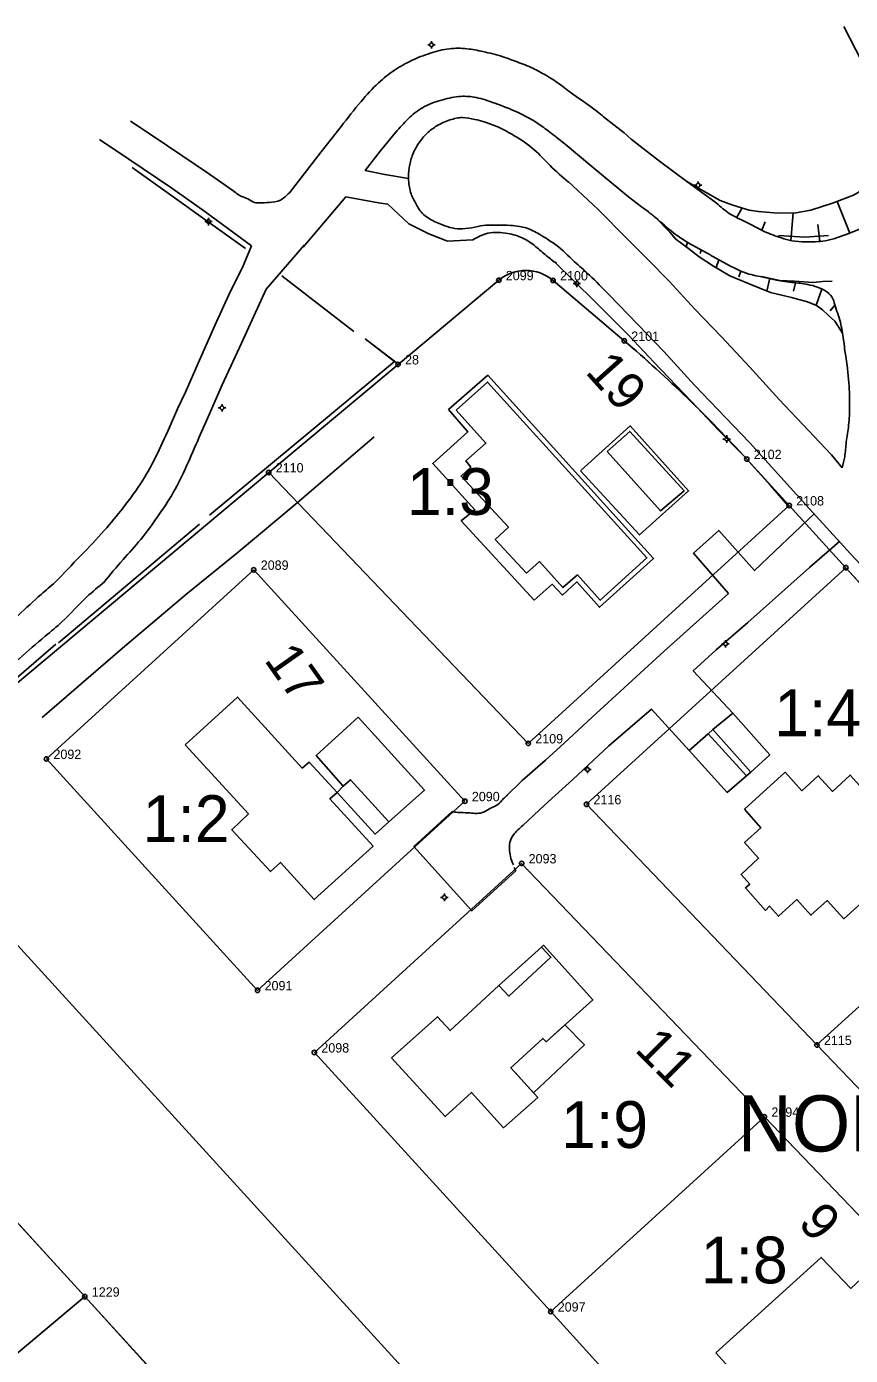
# Model space of a CAD drawing. Extents: x 1517693 to 1518189, y 6494860 to 6495280.
# Drawn here: x 1517936.6 to 1518024.6, y 6495135.7 to 6495277.8 of the extents above; entities that cross this region are included whole.
import ezdxf

# ---------------------------------------------------------------- set-up
doc = ezdxf.new("R2010")
doc.units = 0
for name, color, linetype in [('adress', 7, 'Continuous'), ('bostadshus', 7, 'Continuous'), ('fastighetsbeteckning', 7, 'Continuous'), ('gc_vag', 7, 'Continuous'), ('grans', 7, 'Continuous'), ('granspunkt', 7, 'Continuous'), ('granspunkt_text', 7, 'Continuous'), ('hack', 7, 'Continuous'), ('kvartersgrans', 7, 'Continuous'), ('kvartersgrans_utan_fastgr', 7, 'Continuous'), ('kvartersnamn', 7, 'Continuous'), ('skarmtak', 7, 'Continuous'), ('slant_skraffering', 7, 'Continuous'), ('slantfot', 7, 'Continuous'), ('slantkron', 7, 'Continuous'), ('staket', 7, 'Continuous'), ('stenmur', 7, 'Continuous'), ('stolpe_belysning', 7, 'Continuous'), ('uthus', 7, 'Continuous'), ('vagkant', 7, 'Continuous')]:
    doc.layers.add(name, color=color, linetype=linetype)

msp = doc.modelspace()

# ---------------------------------------------------------------- linework, layer by layer
at = {"layer": 'bostadshus'}
for points in [[(1517982.48, 6495236.79), (1517985.82, 6495239.79), (1518002.87, 6495221.01), (1517997.88, 6495216.47), (1517995.44, 6495219.18), (1517993.9, 6495217.82), (1517991.38, 6495220.6), (1517989.99, 6495219.38), (1517986.66, 6495222.97), (1517988.07, 6495224.27), (1517983.01, 6495229.73), (1517984.06, 6495230.71), (1517983.52, 6495231.36), (1517985.66, 6495233.27), (1517982.48, 6495236.79)], [(1517953.5, 6495201.02), (1517959.1, 6495206.11), (1517966.02, 6495198.53), (1517966.76, 6495199.15), (1517969.76, 6495195.93), (1517968.99, 6495195.25), (1517973.6, 6495190.18), (1517967.31, 6495184.46), (1517963.71, 6495188.43), (1517962.62, 6495187.46), (1517958.49, 6495191.93), (1517960.28, 6495193.62), (1517953.5, 6495201.02)], [(1518013.29, 6495194.12), (1518017.64, 6495198.07), (1518019.42, 6495196.1), (1518021.19, 6495197.7), (1518022.7, 6495196.02), (1518024.6, 6495197.78), (1518028.63, 6495193.3)], [(1518028.31, 6495186.35), (1518023.92, 6495182.41), (1518022.16, 6495184.36), (1518020.4, 6495182.79), (1518018.9, 6495184.47), (1518016.93, 6495182.68), (1518015.98, 6495183.76), (1518015.54, 6495183.31), (1518013.4, 6495185.71), (1518013.86, 6495186.11), (1518012.94, 6495187.14), (1518014.82, 6495188.89), (1518013.31, 6495190.58), (1518015.04, 6495192.12), (1518013.29, 6495194.12)], [(1517975.57, 6495167.55), (1517980.48, 6495171.93), (1517981.83, 6495170.45), (1517987.06, 6495175.28), (1517988.1, 6495174.14), (1517992.61, 6495178.29), (1517991.59, 6495179.38), (1517991.82, 6495179.58), (1517997.11, 6495173.74), (1517992.09, 6495169.26), (1517991.75, 6495169.62), (1517988.32, 6495166.48), (1517991.2, 6495163.3), (1517987.55, 6495160.07), (1517984.13, 6495163.84), (1517981.3, 6495161.27), (1517975.57, 6495167.55)], [(1518010.24, 6495136.01), (1518021.49, 6495146.21), (1518024.66, 6495142.89), (1518028.99, 6495146.91), (1518039.53, 6495135.57), (1518028.29, 6495125.18), (1518029.76, 6495123.58), (1518022.02, 6495116.58), (1518022.18, 6495116.39), (1518018.47, 6495113.08), (1518013.52, 6495118.58), (1518022.53, 6495126.88), (1518015.48, 6495134.51), (1518013.35, 6495132.59), (1518010.23, 6495136.01)]]:
    msp.add_lwpolyline(points, dxfattribs=at)
at = {"layer": 'gc_vag'}
for p, q in [((1517965.26, 6495260.82), (1517964.65, 6495260.03)), ((1517970.67, 6495259.61), (1517966.11, 6495254.21))]:
    msp.add_line(p, q, dxfattribs=at)
for points in [[(1517998.25, 6495268.16), (1518000.45, 6495266.43), (1518001.2, 6495265.76)], [(1517958.87, 6495260.1), (1517955.99, 6495262.08), (1517950.2, 6495266.03), (1517947.68, 6495267.69)], [(1517970.19, 6495267.12), (1517968.06, 6495264.42), (1517965.26, 6495260.82)], [(1517976.19, 6495266.7), (1517974.34, 6495264.49), (1517972.76, 6495262.43), (1517974.85, 6495261.97), (1517977.4, 6495261.55)], [(1517947.49, 6495263.61), (1517944.35, 6495265.74)], [(1517993.91, 6495265.4), (1517997.19, 6495262.67), (1517999.04, 6495261.12), (1518000.89, 6495259.61), (1518002.28, 6495258.52), (1518002.99, 6495258.03)], [(1518010.15, 6495259.08), (1518007.15, 6495261.25), (1518004.22, 6495263.42), (1518001.2, 6495265.76)], [(1517960.6, 6495254.37), (1517955.6, 6495258.02), (1517952.07, 6495260.53), (1517947.49, 6495263.61)], [(1517975.17, 6495258.82), (1517974.19, 6495258.97), (1517970.67, 6495259.61)], [(1517975.17, 6495258.82), (1517977.41, 6495256.72), (1517979.57, 6495255.64), (1517981.57, 6495254.87), (1517984.25, 6495255)], [(1517960.6, 6495254.37), (1517959.63, 6495252.05), (1517958.37, 6495249.52), (1517956.69, 6495245.83), (1517954.9, 6495241.83), (1517953.53, 6495238.72), (1517952.69, 6495236.93), (1517951.8, 6495234.88)], [(1517966.27, 6495254.47), (1517962.16, 6495249.73), (1517959.53, 6495243.94), (1517957.48, 6495239.51), (1517955.85, 6495235.83), (1517954.98, 6495233.83)], [(1517993.02, 6495252.63), (1517997.24, 6495248.49), (1518000.94, 6495244.79), (1518003.63, 6495241.91)], [(1518003.63, 6495241.88), (1518003.63, 6495241.91), (1518007.63, 6495237.7), (1518010.48, 6495234.7), (1518013.14, 6495232.03), (1518016.08, 6495228.73), (1518017.93, 6495226.61)], [(1518020.74, 6495225.7), (1518014.37, 6495219.64), (1518010.55, 6495223.93), (1518007.87, 6495221.49), (1518011.61, 6495217.19)], [(1518023.5, 6495222.78), (1518020.24, 6495219.96), (1518013.66, 6495214.09)], [(1518011.61, 6495217.19), (1518004.71, 6495211.01), (1517997.03, 6495203.95)], [(1518013.66, 6495214.09), (1518010.26, 6495211.17), (1518007.82, 6495208.93), (1518012.07, 6495204.4)], [(1518007.39, 6495200.41), (1518003.36, 6495204.82), (1517998.81, 6495200.9), (1517994.94, 6495197.32)], [(1517987.77, 6495195.46), (1517989.52, 6495197.19), (1517992.05, 6495199.37), (1517994.02, 6495201.19), (1517997.03, 6495203.95)], [(1517994.94, 6495197.32), (1517991.91, 6495194.55), (1517989.62, 6495192.39)], [(1517988.68, 6495187.89), (1517988.86, 6495187.55), (1517984.15, 6495183.26), (1517977.97, 6495190.13), (1517982.05, 6495193.87)]]:
    msp.add_lwpolyline(points, dxfattribs=at)
for points in [[(1517970.19, 6495267.12), (1517972.31, 6495269.79), (1517974.19, 6495271.79), (1517975.88, 6495273.13), (1517977.7, 6495274.16), (1517979.7, 6495274.95), (1517981.76, 6495275.43), (1517983.64, 6495275.43), (1517985.34, 6495275.13), (1517987.46, 6495274.58), (1517988.79, 6495274.1), (1517990.49, 6495273.43), (1517991.89, 6495272.7), (1517993.34, 6495271.79), (1517994.8, 6495270.7), (1517996.86, 6495269.25), (1517998.25, 6495268.16)], [(1517976.19, 6495266.7), (1517977.52, 6495268.1), (1517979.1, 6495269.25), (1517981.04, 6495269.98), (1517982.98, 6495270.34), (1517984.61, 6495270.22), (1517986.61, 6495269.61), (1517989.04, 6495268.64), (1517990.67, 6495267.79), (1517992.01, 6495266.88), (1517994.1, 6495265.25)], [(1517964.65, 6495260.03), (1517963.69, 6495259.26), (1517962.48, 6495259), (1517961.53, 6495258.95), (1517960.91, 6495259), (1517960.22, 6495259.37), (1517959.48, 6495259.68), (1517958.48, 6495260.37)], [(1518002.9, 6495258.1), (1518003.79, 6495257.38), (1518005.71, 6495255.76), (1518007.62, 6495254.49), (1518009.19, 6495253.64), (1518010.77, 6495252.74), (1518012.34, 6495251.93), (1518013.53, 6495251.42), (1518014.51, 6495251.17), (1518018.34, 6495250.45), (1518020.08, 6495250.23), (1518021.1, 6495249.94), (1518022.12, 6495249.43), (1518022.76, 6495248.7), (1518023.02, 6495247.85), (1518023.36, 6495246.87), (1518023.78, 6495245.04), (1518024.04, 6495243.13)], [(1518029.88, 6495259.08), (1518028.1, 6495257.68), (1518026.44, 6495256.57), (1518024.36, 6495255.64), (1518021.93, 6495254.91), (1518019.81, 6495254.79), (1518018.36, 6495254.91), (1518017.25, 6495255.21), (1518015.42, 6495255.89), (1518013.77, 6495256.74), (1518011.51, 6495257.93), (1518010.15, 6495259.08)], [(1517984.25, 6495255), (1517985.06, 6495255.42), (1517985.85, 6495255.7), (1517986.97, 6495255.79), (1517988, 6495255.67), (1517988.82, 6495255.49), (1517989.55, 6495255.21), (1517990.34, 6495254.76), (1517991, 6495254.27), (1517992.15, 6495253.3), (1517993.24, 6495252.46)], [(1518024.04, 6495243.13), (1518024.44, 6495240.07), (1518024.53, 6495237.26), (1518024.44, 6495235.17), (1518024.19, 6495233.39), (1518024.02, 6495231.81), (1518023.76, 6495230.62)], [(1517939.59, 6495218.37), (1517942.35, 6495221.24), (1517944.87, 6495223.93), (1517946.87, 6495226.35), (1517948.98, 6495229.3), (1517950.35, 6495231.77), (1517951.82, 6495234.93)], [(1517944.8, 6495218.37), (1517946.87, 6495220.82), (1517948.77, 6495222.98), (1517950.56, 6495225.4), (1517952.24, 6495227.98), (1517953.66, 6495230.83), (1517954.98, 6495233.83)], [(1517908.48, 6495189.97), (1517911.48, 6495192.18), (1517914.11, 6495193.92), (1517915.85, 6495195.13), (1517917.53, 6495196.29), (1517920.21, 6495198.13), (1517923.16, 6495200.18), (1517927.63, 6495203.66), (1517930.21, 6495205.55), (1517933.32, 6495208.08), (1517935.79, 6495210.24), (1517938.53, 6495212.61), (1517940.37, 6495214.19), (1517943, 6495216.82), (1517944.9, 6495218.45)], [(1517922.49, 6495204.07), (1517925.48, 6495206.4), (1517929, 6495209.19), (1517933.26, 6495212.66), (1517938.11, 6495217.09), (1517939.63, 6495218.4)], [(1517982.05, 6495193.87), (1517982.65, 6495193.79), (1517983.76, 6495193.74), (1517984.49, 6495193.68), (1517985.26, 6495193.76), (1517985.81, 6495194.03), (1517986.39, 6495194.34), (1517987.1, 6495194.76), (1517987.55, 6495195.26), (1517987.97, 6495195.63)], [(1517989.62, 6495192.39), (1517988.6, 6495191.37), (1517988.23, 6495190.55), (1517988.2, 6495189.68), (1517988.34, 6495188.87), (1517988.47, 6495188.47), (1517988.62, 6495188.18)]]:
    msp.add_spline(points, degree=3, dxfattribs=at)
at = {"layer": 'grans'}
for p, q in [((1517976.27, 6495241.68), (1517987.04, 6495250.68)), ((1518000.45, 6495244.2), (1517992.84, 6495250.66)), ((1517976.27, 6495241.68), (1517962.44, 6495230.13)), ((1518018.08, 6495226.6), (1518013.55, 6495231.56)), ((1517962.44, 6495230.13), (1517921.04, 6495195.52)), ((1517962.44, 6495230.13), (1517990.19, 6495201.16)), ((1517990.19, 6495201.16), (1518018.08, 6495226.6)), ((1517938.68, 6495199.5), (1517960.84, 6495219.72)), ((1517960.84, 6495219.72), (1517983.41, 6495194.98)), ((1517996.41, 6495194.65), (1518024.14, 6495219.95)), ((1518024.14, 6495219.95), (1518048.14, 6495193.63)), ((1517961.25, 6495174.76), (1517938.68, 6495199.5)), ((1517983.41, 6495194.98), (1517961.25, 6495174.76)), ((1518021.05, 6495168.92), (1517996.41, 6495194.65)), ((1518048.14, 6495193.63), (1518021.05, 6495168.92)), ((1517967.32, 6495168.11), (1517989.48, 6495188.33)), ((1517989.48, 6495188.33), (1518015.43, 6495161.24)), ((1517905.68, 6495182.68), (1517942.78, 6495142.01)), ((1518021.05, 6495168.92), (1518047.23, 6495141.59)), ((1517992.59, 6495140.41), (1517967.32, 6495168.11)), ((1518015.43, 6495161.24), (1517992.59, 6495140.41)), ((1518041.37, 6495134.15), (1518015.43, 6495161.24)), ((1517942.78, 6495142.01), (1517887.66, 6495095.94)), ((1517942.78, 6495142.01), (1518054.69, 6495019.3)), ((1517992.59, 6495140.41), (1518017.86, 6495112.7))]:
    msp.add_line(p, q, dxfattribs=at)
for centre, radius, start, end in [((1517989.93, 6495247.23), 4.5, 49.6994, 129.8503), ((1517907.57, 6495134.85), 143.47, 42.3829, 49.656)]:
    msp.add_arc(centre, radius, start, end, dxfattribs=at)
at = {"layer": 'granspunkt'}
for centre in [(1517987.04, 6495250.68), (1517992.84, 6495250.66), (1518000.45, 6495244.2), (1517976.27, 6495241.68), (1518013.55, 6495231.56), (1517962.44, 6495230.13), (1518018.08, 6495226.6), (1517960.84, 6495219.72), (1518024.14, 6495219.95), (1517990.19, 6495201.16), (1517938.68, 6495199.5), (1517983.41, 6495194.98), (1517996.41, 6495194.65), (1517989.48, 6495188.33), (1517961.25, 6495174.76), (1518021.05, 6495168.92), (1517967.32, 6495168.11), (1518015.43, 6495161.24), (1517942.78, 6495142.01), (1517992.59, 6495140.41)]:
    msp.add_circle(centre, 0.237, dxfattribs=at)
at = {"layer": 'hack'}
for p, q in [((1517959.97, 6495254.09), (1517947.86, 6495262.75)), ((1517971.53, 6495245.2), (1517963.85, 6495251.15)), ((1517972.74, 6495244.41), (1517976.21, 6495241.78)), ((1517928.27, 6495201.92), (1517939.69, 6495211.77))]:
    msp.add_line(p, q, dxfattribs=at)
msp.add_lwpolyline([(1517973.71, 6495233.93), (1517965.5, 6495226.88), (1517959.19, 6495221.61), (1517953.72, 6495217.19), (1517946.82, 6495211.35), (1517938.22, 6495203.92)], dxfattribs=at)
at = {"layer": 'kvartersgrans'}
for p, q in [((1517992.84, 6495250.66), (1518000.45, 6495244.2)), ((1518013.55, 6495231.56), (1518018.08, 6495226.6)), ((1517962.44, 6495230.13), (1517921.04, 6495195.52))]:
    msp.add_line(p, q, dxfattribs=at)
for points in [[(1517962.44, 6495230.13), (1517976.27, 6495241.68), (1517987.04, 6495250.68)], [(1518024.14, 6495219.95), (1518048.14, 6495193.63), (1518073.64, 6495165.68)], [(1517905.68, 6495182.68), (1517942.78, 6495142.01), (1518054.69, 6495019.3)]]:
    msp.add_lwpolyline(points, dxfattribs=at)
for centre, radius, start, end in [((1517989.93, 6495247.23), 4.5, 49.6994, 129.8503), ((1517907.58, 6495134.86), 143.46, 42.3826, 49.6563)]:
    msp.add_arc(centre, radius, start, end, dxfattribs=at)
at = {"layer": 'kvartersgrans_utan_fastgr'}
for p, q in [((1518018.08, 6495226.6), (1518024.14, 6495219.95)), ((1517921.04, 6495195.52), (1518074.11, 6495027.69))]:
    msp.add_line(p, q, dxfattribs=at)
at = {"layer": 'skarmtak'}
for p, q in [((1517981.67, 6495236.86), (1517985.85, 6495240.55)), ((1517970.41, 6495196.58), (1517969.76, 6495195.93)), ((1517987.06, 6495175.28), (1517991.59, 6495179.38))]:
    msp.add_line(p, q, dxfattribs=at)
for points in [[(1517985.85, 6495240.55), (1518003.59, 6495220.94), (1517997.81, 6495215.72), (1517995.37, 6495218.42), (1517993.84, 6495217.02), (1517992.75, 6495218.17), (1517990.81, 6495216.49), (1517983.03, 6495224.95), (1517984.48, 6495226.14), (1517979.97, 6495231.08), (1517983.72, 6495234.49), (1517981.67, 6495236.86)], [(1517995.8, 6495230.34), (1518001.07, 6495235.1), (1518007.33, 6495228.18), (1518002.07, 6495223.45), (1517995.79, 6495230.31)], [(1518009.92, 6495202.64), (1518012.07, 6495204.4), (1518016.01, 6495199.93), (1518013.98, 6495198.1)], [(1518009.41, 6495202.19), (1518007.39, 6495200.41), (1518011.44, 6495195.92), (1518013.51, 6495197.71)], [(1517969.76, 6495195.93), (1517973.84, 6495191.47), (1517975.27, 6495192.79)], [(1517988.32, 6495166.48), (1517991.75, 6495169.62), (1517992.09, 6495169.26), (1517994.1, 6495171.06), (1517996.19, 6495168.92), (1517990.75, 6495163.8), (1517988.79, 6495165.96)]]:
    msp.add_lwpolyline(points, dxfattribs=at)
at = {"layer": 'slant_skraffering'}
for p, q in [((1518012.46, 6495257.35), (1518013.07, 6495258.41)), ((1518024.57, 6495255.72), (1518023.21, 6495259.11)), ((1518015.15, 6495256.03), (1518015.52, 6495256.92)), ((1518018.27, 6495254.93), (1518018.5, 6495257.89)), ((1518021.35, 6495254.83), (1518021.13, 6495256.63)), ((1518007.2, 6495254.73), (1518007.03, 6495254.18)), ((1518008.66, 6495253.93), (1518008.56, 6495253.53)), ((1518010.26, 6495252.04), (1518010.57, 6495252.86)), ((1518012.93, 6495251.66), (1518012.71, 6495251.05)), ((1518018.76, 6495250.39), (1518018.54, 6495249.52)), ((1518021.57, 6495249.74), (1518020.96, 6495248)), ((1518022.97, 6495248), (1518022.48, 6495247.4))]:
    msp.add_line(p, q, dxfattribs=at)
msp.add_lwpolyline([(1518016.02, 6495250.89), (1518015.7, 6495249.52), (1518015.7, 6495249.52)], dxfattribs=at)
at = {"layer": 'slantfot'}
for points in [[(1518033.82, 6495267.18), (1518031.03, 6495264.49), (1518029.1, 6495262.4), (1518026.86, 6495260.87), (1518024.95, 6495259.76), (1518022.7, 6495258.91), (1518020.4, 6495258.19), (1518018.78, 6495257.89), (1518016.87, 6495257.85), (1518014.79, 6495258.02), (1518013.81, 6495258.19), (1518012.07, 6495258.7), (1518010.7, 6495259.21), (1518007.15, 6495261.25)], [(1518023.78, 6495245.04), (1518022.97, 6495246.32), (1518022.25, 6495246.96), (1518021.66, 6495247.51), (1518021.02, 6495247.98), (1518020.04, 6495248.36), (1518018.34, 6495248.83), (1518016.08, 6495249.38), (1518013.79, 6495250.28), (1518011.75, 6495251.17), (1518010, 6495252.19), (1518008.47, 6495253.17), (1518007.32, 6495254.06), (1518005.96, 6495255.08), (1518005.32, 6495255.81), (1518003.79, 6495257.38)]]:
    msp.add_lwpolyline(points, dxfattribs=at)
at = {"layer": 'slantkron'}
msp.add_lwpolyline([(1518023.91, 6495277.8), (1518025.86, 6495274.06), (1518027.27, 6495270.49), (1518028.2, 6495267.51), (1518028.88, 6495264.27), (1518029.1, 6495262.4)], dxfattribs=at)
at = {"layer": 'staket'}
for p, q in [((1517963.85, 6495251.15), (1517971.53, 6495245.2)), ((1517939.98, 6495211.93), (1517955.03, 6495224.61))]:
    msp.add_line(p, q, dxfattribs=at)
for points in [[(1518022.29, 6495255.47), (1518019.74, 6495255.3), (1518016.93, 6495255.47)], [(1518015.11, 6495251.08), (1518017.1, 6495250.66), (1518018.64, 6495250.57), (1518020.63, 6495250.45), (1518021.66, 6495250.53), (1518022.68, 6495250.57)], [(1517956.11, 6495225.56), (1517975.9, 6495241.99), (1517972.74, 6495244.41)]]:
    msp.add_lwpolyline(points, dxfattribs=at)
at = {"layer": 'stenmur'}
for p, q in [((1518009.41, 6495202.19), (1518009.92, 6495202.64)), ((1518013.98, 6495198.1), (1518009.92, 6495202.64)), ((1518013.51, 6495197.71), (1518009.41, 6495202.19)), ((1518013.51, 6495197.71), (1518013.98, 6495198.1)), ((1518013.56, 6495197.67), (1518013.56, 6495197.67))]:
    msp.add_line(p, q, dxfattribs=at)
at = {"layer": 'stolpe_belysning'}
for p, q in [((1517979.64, 6495275.85), (1517979.44, 6495275.85)), ((1517979.84, 6495276.05), (1517979.84, 6495276.25)), ((1517979.84, 6495275.65), (1517979.84, 6495275.45)), ((1517980.04, 6495275.85), (1517980.24, 6495275.85)), ((1518008.34, 6495261.03), (1518008.34, 6495261.23)), ((1518008.14, 6495260.83), (1518007.94, 6495260.83)), ((1518008.34, 6495260.63), (1518008.34, 6495260.43)), ((1518008.54, 6495260.83), (1518008.74, 6495260.83)), ((1517955.8, 6495256.95), (1517955.6, 6495256.95)), ((1517956, 6495257.15), (1517956, 6495257.35)), ((1517956, 6495256.75), (1517956, 6495256.55)), ((1517956.2, 6495256.95), (1517956.4, 6495256.95)), ((1517995.19, 6495250.34), (1517994.99, 6495250.34)), ((1517995.39, 6495250.54), (1517995.39, 6495250.74)), ((1517995.39, 6495250.14), (1517995.39, 6495249.94)), ((1517995.59, 6495250.34), (1517995.79, 6495250.34)), ((1517957.25, 6495237.04), (1517957.05, 6495237.04)), ((1517957.45, 6495237.24), (1517957.45, 6495237.44)), ((1517957.45, 6495236.84), (1517957.45, 6495236.64)), ((1517957.65, 6495237.04), (1517957.85, 6495237.04)), ((1518011.4, 6495233.9), (1518011.4, 6495234.1)), ((1518011.2, 6495233.7), (1518011, 6495233.7)), ((1518011.4, 6495233.5), (1518011.4, 6495233.3)), ((1518011.6, 6495233.7), (1518011.8, 6495233.7)), ((1518011.08, 6495211.8), (1518010.88, 6495211.8)), ((1518011.28, 6495212), (1518011.28, 6495212.2)), ((1518011.28, 6495211.6), (1518011.28, 6495211.4)), ((1518011.48, 6495211.8), (1518011.68, 6495211.8)), ((1517996.33, 6495198.37), (1517996.13, 6495198.37)), ((1517996.53, 6495198.57), (1517996.53, 6495198.77)), ((1517996.73, 6495198.37), (1517996.93, 6495198.37)), ((1517996.53, 6495198.17), (1517996.53, 6495197.97)), ((1517981.02, 6495184.7), (1517980.82, 6495184.7)), ((1517981.22, 6495184.9), (1517981.22, 6495185.1)), ((1517981.22, 6495184.5), (1517981.22, 6495184.3)), ((1517981.42, 6495184.7), (1517981.62, 6495184.7))]:
    msp.add_line(p, q, dxfattribs=at)
for centre in [(1517979.84, 6495275.85), (1518008.34, 6495260.83), (1517956, 6495256.95), (1517995.39, 6495250.34), (1517957.45, 6495237.04), (1518011.4, 6495233.7), (1518011.28, 6495211.8), (1517996.53, 6495198.37), (1517981.22, 6495184.7)]:
    msp.add_circle(centre, 0.2, dxfattribs=at)
at = {"layer": 'uthus'}
for points in [[(1517998.64, 6495232.38), (1518001.04, 6495234.52), (1518006.85, 6495228.15), (1518004.33, 6495226.02), (1517998.64, 6495232.38)], [(1517967.5, 6495199.87), (1517971.99, 6495203.96), (1517979.09, 6495196.15), (1517975.27, 6495192.79), (1517971.2, 6495197.27), (1517970.41, 6495196.58), (1517967.5, 6495199.87)]]:
    msp.add_lwpolyline(points, dxfattribs=at)
at = {"layer": 'vagkant'}
for points in [[(1517994.44, 6495261.23), (1517997.61, 6495258.27), (1518000.8, 6495255.09), (1518003.01, 6495252.88), (1518005.25, 6495250.57), (1518008.01, 6495247.6), (1518010.86, 6495244.63)], [(1517998.77, 6495249.18), (1518001.95, 6495245.9), (1518004.68, 6495243.05)], [(1518010.86, 6495244.63), (1518013.86, 6495241.39), (1518017.01, 6495237.93), (1518020.13, 6495234.6), (1518022.62, 6495232.02), (1518023.76, 6495230.64)], [(1518004.68, 6495243.05), (1518007.95, 6495239.48), (1518013.83, 6495233.35), (1518019.86, 6495226.68)], [(1518019.86, 6495226.68), (1518024.65, 6495221.44), (1518027.44, 6495218.44), (1518030.07, 6495215.49), (1518034.35, 6495210.92)]]:
    msp.add_lwpolyline(points, dxfattribs=at)
for points in [[(1517994.49, 6495261.18), (1517992.52, 6495262.94), (1517990.83, 6495264.64), (1517988.7, 6495266.13), (1517987.01, 6495267.03), (1517985.49, 6495267.61), (1517984.46, 6495267.88), (1517983.16, 6495268.07), (1517981.82, 6495267.82), (1517980.43, 6495267.19), (1517979.37, 6495266.4), (1517978.46, 6495265.31), (1517977.79, 6495264), (1517977.46, 6495262.73), (1517977.4, 6495261.37), (1517977.67, 6495259.91), (1517978.19, 6495258.82), (1517978.49, 6495258.3), (1517979.64, 6495257.24), (1517981.01, 6495256.6), (1517982.07, 6495256.27), (1517983.16, 6495256.18), (1517984.49, 6495256.36), (1517985.67, 6495256.57), (1517986.92, 6495256.57), (1517988.28, 6495256.54), (1517989.25, 6495256.42), (1517989.95, 6495256.27), (1517991.37, 6495255.6), (1517992.25, 6495255.06), (1517993.43, 6495254.27)], [(1517993.43, 6495254.27), (1517995.34, 6495252.48), (1517996.74, 6495251.21), (1517998.77, 6495249.18)]]:
    msp.add_spline(points, degree=3, dxfattribs=at)

# ---------------------------------------------------------------- texts
at = {"layer": 'adress'}
for s, rotation, p in [('19', 311.858, (1517996.18, 6495240.83)), ('17', 305.1968, (1517961.88, 6495210.07)), ('11', 314.9833, (1518001.46, 6495168.33)), ('9', 311.9627, (1518018.91, 6495149.81))]:
    msp.add_text(s, height=4, rotation=rotation, dxfattribs=at).set_placement(p)
at = {"layer": 'fastighetsbeteckning'}
for s, p in [('1:3', (1517977.22, 6495225.59)), ('1:4', (1518016.48, 6495201.93)), ('1:2', (1517948.97, 6495190.62)), ('1:9', (1517993.7, 6495157.91)), ('1:8', (1518008.63, 6495143.43))]:
    msp.add_text(s, height=5, rotation=0.0021, dxfattribs=at).set_placement(p)
at = {"layer": 'granspunkt_text'}
for s, p in [('2099', (1517987.79, 6495250.68)), ('2100', (1517993.59, 6495250.66)), ('2101', (1518001.2, 6495244.2)), ('28', (1517977.02, 6495241.68)), ('2102', (1518014.3, 6495231.56)), ('2110', (1517963.19, 6495230.13)), ('2108', (1518018.83, 6495226.6)), ('2089', (1517961.59, 6495219.72)), ('2109', (1517990.94, 6495201.16)), ('2092', (1517939.43, 6495199.5)), ('2090', (1517984.16, 6495194.98)), ('2116', (1517997.16, 6495194.65)), ('2093', (1517990.23, 6495188.33)), ('2091', (1517962, 6495174.76)), ('2115', (1518021.8, 6495168.92)), ('2098', (1517968.07, 6495168.11)), ('2094', (1518016.18, 6495161.24)), ('1229', (1517943.53, 6495142.01)), ('2097', (1517993.34, 6495140.41))]:
    msp.add_text(s, height=1, dxfattribs=at).set_placement(p)
at = {"layer": 'kvartersnamn'}
msp.add_text('NORDEN', height=6, rotation=0.0021, dxfattribs=at).set_placement((1518012.58, 6495157.53))

doc.saveas('drawing.dxf')
